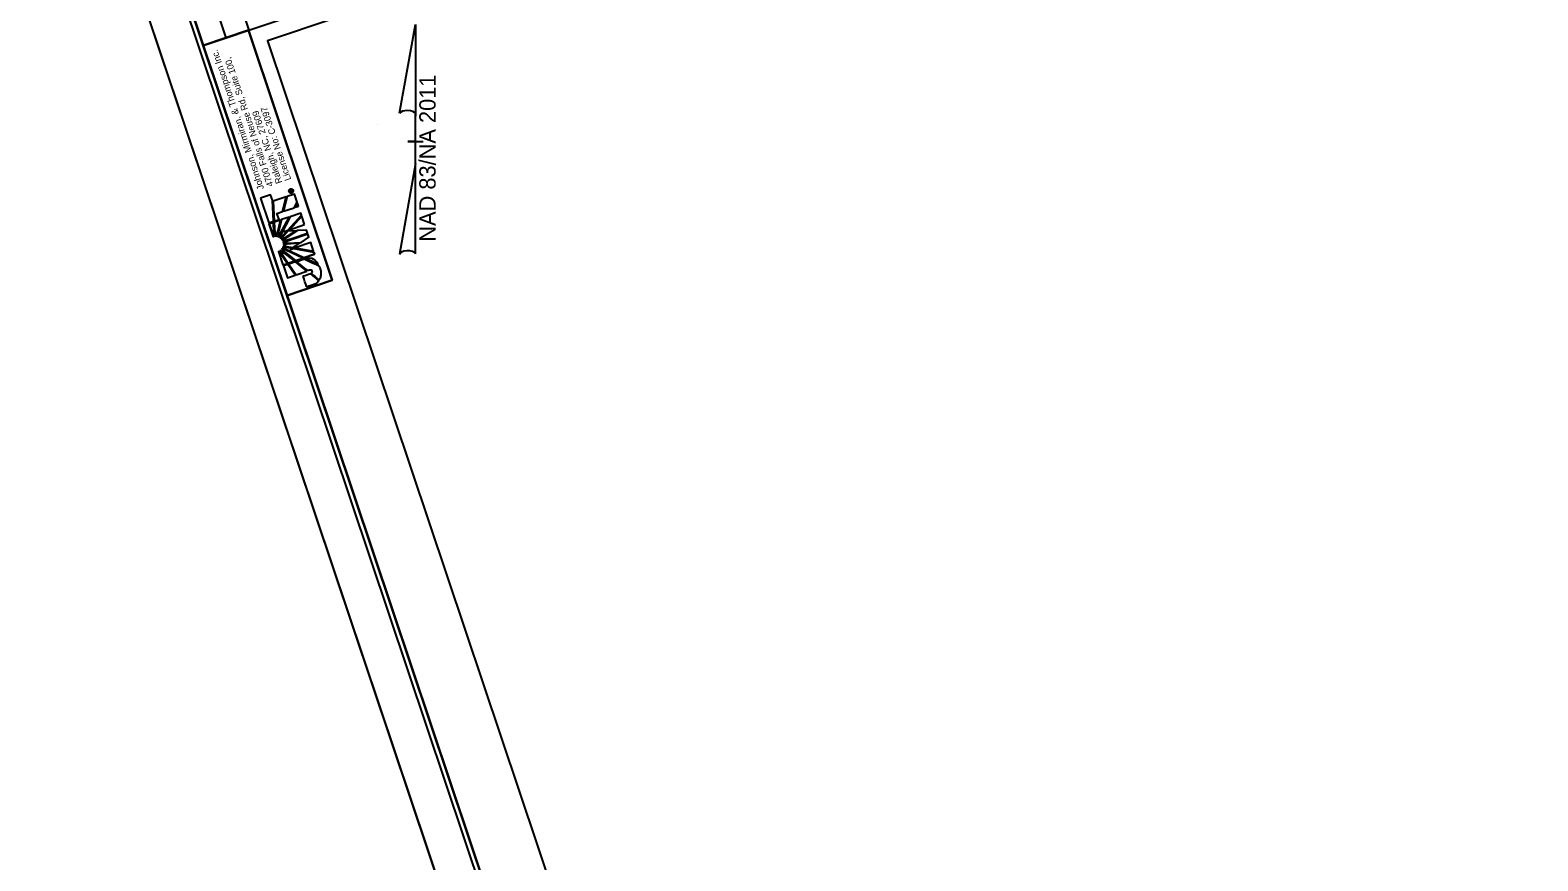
# Model space of a CAD drawing. Extents: x 1615436 to 1617010, y 903110 to 905055.
# Drawn here: x 1615436 to 1616223, y 904083 to 904516 of the extents above; entities that cross this region are included whole.
import ezdxf

# ---------------------------------------------------------------- set-up
doc = ezdxf.new("R2010")
doc.units = 0
for name, color, linetype in [('Default', 7, 'Continuous'), ('Exist Plan Preparation Drainage Flow Arrows', 7, 'Continuous'), ('Exist Plan Preparation Drainage Notes Label', 7, 'Continuous'), ('Exist Structure Minor Pipes CMP 24 Inch Text', 7, 'Continuous'), ('Exist Structure Minor Pipes RCP 18 Inch', 7, 'Continuous'), ('Prop Drainage Structure Catch Basin Grate 840 03E CELL', 7, 'Continuous'), ('Prop Drainage Structure Plot Symbol 50 Scale', 7, 'Continuous'), ('Prop Plan Preparation Sag Label', 7, 'Continuous'), ('Scratch_Level_8', 7, 'Continuous')]:
    doc.layers.add(name, color=color, linetype=linetype)

msp = doc.modelspace()

# ---------------------------------------------------------------- linework, layer by layer
at = {"layer": 'Default'}
for p, q in [((1615574.29, 904430.4), (1615570.5, 904429.12)), ((1615571.56, 904431.69), (1615571.75, 904431.76)), ((1615571.75, 904431.76), (1615571.56, 904431.69)), ((1615572.11, 904431.88), (1615572.09, 904431.93)), ((1615572.11, 904431.88), (1615572.29, 904431.94)), ((1615572.29, 904431.94), (1615572.11, 904431.88)), ((1615572.24, 904431.49), (1615572.11, 904431.88)), ((1615573.17, 904431.81), (1615572.24, 904431.49)), ((1615572.28, 904431.96), (1615572.29, 904431.94)), ((1615572.29, 904431.94), (1615572.34, 904431.77)), ((1615572.34, 904431.77), (1615572.56, 904431.84)), ((1615572.51, 904432.01), (1615572.5, 904432.02)), ((1615572.51, 904432.01), (1615572.68, 904432.07)), ((1615572.68, 904432.07), (1615572.51, 904432.01)), ((1615572.56, 904431.84), (1615572.51, 904432.01)), ((1615572.67, 904432.08), (1615572.68, 904432.07)), ((1615572.68, 904432.07), (1615572.73, 904431.9)), ((1615572.73, 904431.9), (1615573.1, 904432.02)), ((1615573.1, 904432.02), (1615573.17, 904431.81)), ((1615573.41, 904432.31), (1615573.4, 904432.32)), ((1615573.41, 904432.31), (1615573.61, 904432.38)), ((1615573.61, 904432.38), (1615573.41, 904432.31)), ((1615573.61, 904432.39), (1615573.61, 904432.38)), ((1615575.68, 904426.26), (1615574.29, 904430.4)), ((1615561.93, 904429.99), (1615556.67, 904428.22)), ((1615556.67, 904428.22), (1615560.99, 904415.4)), ((1615562.85, 904427.26), (1615561.93, 904429.99)), ((1615563.42, 904416.21), (1615562.85, 904427.26)), ((1615570.03, 904428.96), (1615563.3, 904426.69)), ((1615563.3, 904426.69), (1615563.78, 904416.34)), ((1615568.15, 904421.29), (1615570.03, 904428.96)), ((1615570.5, 904429.12), (1615568.66, 904421.46)), ((1615568.66, 904421.46), (1615574.11, 904423.3)), ((1615574.11, 904423.3), (1615575.68, 904426.26)), ((1615575.88, 904425.66), (1615574.7, 904423.5)), ((1615574.7, 904423.5), (1615576.42, 904424.08)), ((1615576.42, 904424.08), (1615575.88, 904425.66)), ((1615560.99, 904415.4), (1615563.35, 904416.19)), ((1615563.38, 904415.67), (1615561.18, 904414.93)), ((1615561.18, 904414.93), (1615563.43, 904408.16)), ((1615563.35, 904416.19), (1615563.42, 904416.21)), ((1615563.66, 904410.14), (1615563.38, 904415.67)), ((1615563.78, 904416.34), (1615563.82, 904416.35)), ((1615563.82, 904416.35), (1615566.28, 904417.18)), ((1615567.08, 904416.88), (1615563.84, 904415.83)), ((1615563.84, 904415.83), (1615564.16, 904410.12)), ((1615565.22, 904420.31), (1615568.15, 904421.29)), ((1615566.28, 904417.18), (1615565.22, 904420.31)), ((1615565.78, 904411.42), (1615567.08, 904416.88)), ((1615567.63, 904417.06), (1615566.06, 904410.69)), ((1615566.96, 904409.69), (1615571.53, 904418.37)), ((1615572.17, 904418.59), (1615567.36, 904409.52)), ((1615571.53, 904418.37), (1615567.63, 904417.06)), ((1615570.81, 904411.51), (1615578, 904419.36)), ((1615578.14, 904418.84), (1615571.68, 904411.8)), ((1615571.68, 904411.8), (1615579.62, 904414.47)), ((1615577.64, 904420.43), (1615572.17, 904418.59)), ((1615578, 904419.36), (1615577.64, 904420.43)), ((1615579.62, 904414.47), (1615578.14, 904418.84)), ((1615563.43, 904408.16), (1615563.66, 904410.14)), ((1615564.16, 904410.12), (1615564.55, 904408.16)), ((1615564.55, 904408.16), (1615565.78, 904411.42)), ((1615566.06, 904410.69), (1615565.68, 904407.94)), ((1615565.68, 904407.94), (1615566.96, 904409.69)), ((1615567.36, 904409.52), (1615566.65, 904407.47)), ((1615566.65, 904407.47), (1615568.36, 904408.88)), ((1615568.64, 904408.49), (1615567.49, 904406.79)), ((1615567.49, 904406.79), (1615569.37, 904407.65)), ((1615569.77, 904407.37), (1615568.09, 904405.91)), ((1615568.09, 904405.91), (1615573.01, 904407.22)), ((1615568.36, 904408.88), (1615570.34, 904411)), ((1615573.15, 904406.78), (1615568.43, 904404.9)), ((1615570.97, 904411.03), (1615568.64, 904408.49)), ((1615569.03, 904410.91), (1615570.81, 904411.51)), ((1615570.34, 904411), (1615569.03, 904410.91)), ((1615569.37, 904407.65), (1615575, 904411.31)), ((1615575.87, 904411.38), (1615569.77, 904407.37)), ((1615575, 904411.31), (1615570.97, 904411.03)), ((1615573.01, 904407.22), (1615581.14, 904409.95)), ((1615581.28, 904409.52), (1615573.15, 904406.78)), ((1615580.57, 904411.65), (1615575.87, 904411.38)), ((1615577.83, 904405.22), (1615581.85, 904407.85)), ((1615581.14, 904409.95), (1615580.57, 904411.65)), ((1615581.85, 904407.85), (1615581.28, 904409.52)), ((1615567.41, 904398.9), (1615566.05, 904400.39)), ((1615566.05, 904400.39), (1615568.36, 904393.53)), ((1615569.88, 904399.14), (1615566.97, 904400.97)), ((1615566.97, 904400.97), (1615567.89, 904399.06)), ((1615570.54, 904394.26), (1615567.41, 904398.9)), ((1615569.8, 904401.17), (1615567.75, 904401.79)), ((1615567.75, 904401.79), (1615569.71, 904399.86)), ((1615567.89, 904399.06), (1615571.02, 904394.42)), ((1615568.25, 904402.74), (1615570.04, 904401.54)), ((1615570.45, 904402.66), (1615568.25, 904402.74)), ((1615568.43, 904404.9), (1615570.66, 904404.72)), ((1615570.44, 904404.27), (1615568.5, 904403.8)), ((1615568.5, 904403.8), (1615570.45, 904403.12)), ((1615569.71, 904399.86), (1615574.85, 904395.71)), ((1615578.66, 904396.99), (1615569.8, 904401.17)), ((1615574.32, 904395.53), (1615569.88, 904399.14)), ((1615570.04, 904401.54), (1615579.3, 904397.21)), ((1615577.06, 904404.74), (1615570.44, 904404.27)), ((1615570.45, 904403.12), (1615573.72, 904402.53)), ((1615573.21, 904402.16), (1615570.45, 904402.66)), ((1615570.66, 904404.72), (1615577.83, 904405.22)), ((1615572.2, 904401.49), (1615573.21, 904402.16)), ((1615573.81, 904402.03), (1615572.2, 904401.49)), ((1615573.72, 904402.53), (1615577.06, 904404.74)), ((1615584.5, 904400.08), (1615573.81, 904402.03)), ((1615582.81, 904405.1), (1615574.69, 904402.32)), ((1615574.69, 904402.32), (1615584.34, 904400.55)), ((1615579.3, 904397.21), (1615584.84, 904399.08)), ((1615584.34, 904400.55), (1615582.81, 904405.1)), ((1615584.84, 904399.08), (1615584.5, 904400.08)), ((1615568.36, 904393.53), (1615570.54, 904394.26)), ((1615570.96, 904393.7), (1615568.6, 904392.9)), ((1615568.6, 904392.9), (1615570.66, 904386.8)), ((1615574.7, 904388.17), (1615570.96, 904393.7)), ((1615571.02, 904394.42), (1615574.32, 904395.53)), ((1615574.93, 904395.03), (1615571.4, 904393.84)), ((1615571.4, 904393.84), (1615575.17, 904388.32)), ((1615574.85, 904395.71), (1615578.66, 904396.99)), ((1615580.85, 904390.24), (1615574.93, 904395.03)), ((1615570.66, 904386.8), (1615574.7, 904388.17)), ((1615575.17, 904388.32), (1615580.85, 904390.24))]:
    msp.add_line(p, q, dxfattribs=at)
for points in [[(1615594.07, 904385.48), (1615550.29, 904515.85), (1615526.77, 904507.96), (1615570.54, 904377.58)], [(1615563.43, 904408.16), (1615561.18, 904414.93), (1615563.38, 904415.67), (1615563.66, 904410.14)], [(1615584.84, 904399.08), (1615579.3, 904397.21), (1615570.04, 904401.54), (1615568.25, 904402.74), (1615569.97, 904402.73), (1615573.21, 904402.16), (1615572.2, 904401.49), (1615573.81, 904402.03), (1615584.5, 904400.08)]]:
    msp.add_lwpolyline(points, close=True, dxfattribs=at)
for points in [[(1615568.66, 904421.46), (1615574.11, 904423.3), (1615575.68, 904426.26), (1615574.29, 904430.4), (1615570.5, 904429.12), (1615568.66, 904421.46), (1615568.66, 904421.46)], [(1615572.68, 904432.52), (1615572.73, 904432.54), (1615572.77, 904432.56), (1615572.8, 904432.57), (1615572.89, 904432.63), (1615572.96, 904432.44)], [(1615556.67, 904428.22), (1615560.99, 904415.4), (1615563.35, 904416.19), (1615563.42, 904416.21), (1615562.85, 904427.26), (1615561.93, 904429.99), (1615556.67, 904428.22)], [(1615563.78, 904416.34), (1615563.82, 904416.35), (1615566.28, 904417.18), (1615565.22, 904420.31), (1615568.15, 904421.29), (1615570.03, 904428.96), (1615563.3, 904426.69), (1615563.78, 904416.34)], [(1615576.42, 904424.08), (1615576.42, 904424.08), (1615575.88, 904425.66), (1615574.7, 904423.5), (1615576.42, 904424.08)], [(1615563.66, 904410.14), (1615563.38, 904415.67), (1615561.18, 904414.93), (1615563.43, 904408.16), (1615563.66, 904410.14)], [(1615564.55, 904408.16), (1615565.78, 904411.42), (1615567.08, 904416.88), (1615563.84, 904415.83), (1615564.16, 904410.12), (1615564.55, 904408.16)], [(1615565.68, 904407.94), (1615566.96, 904409.69), (1615571.53, 904418.37), (1615567.63, 904417.06), (1615566.06, 904410.69), (1615565.68, 904407.94)], [(1615566.65, 904407.47), (1615568.36, 904408.88), (1615570.34, 904411), (1615569.03, 904410.91), (1615570.81, 904411.51), (1615578, 904419.36), (1615577.64, 904420.43), (1615572.17, 904418.59), (1615567.36, 904409.52), (1615566.65, 904407.47)], [(1615579.62, 904414.47), (1615578.14, 904418.84), (1615571.68, 904411.8), (1615579.62, 904414.47)], [(1615567.49, 904406.79), (1615569.37, 904407.65), (1615575, 904411.31), (1615570.97, 904411.03), (1615568.64, 904408.49), (1615567.49, 904406.79)], [(1615568.09, 904405.91), (1615573.01, 904407.22), (1615581.14, 904409.95), (1615580.57, 904411.65), (1615575.87, 904411.38), (1615569.77, 904407.37), (1615568.09, 904405.91)], [(1615570.66, 904404.72), (1615577.83, 904405.22), (1615581.85, 904407.85), (1615581.28, 904409.52), (1615573.15, 904406.78), (1615568.43, 904404.9), (1615570.66, 904404.72)], [(1615567.41, 904398.9), (1615566.05, 904400.39), (1615568.36, 904393.53), (1615570.54, 904394.26), (1615567.41, 904398.9)], [(1615571.02, 904394.42), (1615574.32, 904395.53), (1615569.88, 904399.14), (1615566.97, 904400.97), (1615567.89, 904399.06), (1615571.02, 904394.42)], [(1615574.85, 904395.71), (1615578.66, 904396.99), (1615569.8, 904401.17), (1615567.75, 904401.79), (1615569.71, 904399.86), (1615574.85, 904395.71)], [(1615568.25, 904402.74), (1615570.04, 904401.54), (1615579.3, 904397.21), (1615584.84, 904399.08), (1615584.5, 904400.08), (1615573.81, 904402.03), (1615572.2, 904401.49), (1615573.21, 904402.16), (1615570.45, 904402.66), (1615568.25, 904402.74)], [(1615568.5, 904403.8), (1615570.45, 904403.12), (1615573.72, 904402.53), (1615577.06, 904404.74), (1615570.44, 904404.27), (1615568.5, 904403.8)], [(1615584.34, 904400.55), (1615582.81, 904405.1), (1615574.69, 904402.32), (1615584.34, 904400.55)], [(1615574.7, 904388.17), (1615570.96, 904393.7), (1615568.6, 904392.9), (1615570.66, 904386.8), (1615574.7, 904388.17)], [(1615580.85, 904390.24), (1615574.93, 904395.03), (1615571.4, 904393.84), (1615575.17, 904388.32), (1615580.85, 904390.24)]]:
    msp.add_lwpolyline(points, dxfattribs=at)
for points, degree in [([(1615571.56, 904431.69), (1615571.46, 904431.98), (1615571.48, 904432.26), (1615571.61, 904432.53), (1615571.72, 904432.79), (1615571.94, 904432.98), (1615572.22, 904433.08)], 3), ([(1615573.61, 904432.38), (1615573.7, 904432.1), (1615573.68, 904431.82), (1615573.55, 904431.55), (1615573.42, 904431.28), (1615573.21, 904431.1), (1615572.92, 904431), (1615572.63, 904430.9), (1615572.35, 904430.92), (1615572.1, 904431.06), (1615571.84, 904431.2), (1615571.65, 904431.4), (1615571.56, 904431.69)], 3), ([(1615573.4, 904432.32), (1615573.33, 904432.55), (1615573.18, 904432.72), (1615572.97, 904432.83), (1615572.75, 904432.93), (1615572.52, 904432.95), (1615572.29, 904432.87), (1615572.06, 904432.79), (1615571.89, 904432.64), (1615571.78, 904432.43), (1615571.68, 904432.21), (1615571.67, 904431.99), (1615571.75, 904431.76)], 3), ([(1615571.75, 904431.76), (1615571.83, 904431.53), (1615571.97, 904431.36), (1615572.18, 904431.25), (1615572.39, 904431.14), (1615572.63, 904431.12), (1615572.85, 904431.2), (1615573.08, 904431.28), (1615573.26, 904431.43), (1615573.37, 904431.65), (1615573.47, 904431.86), (1615573.48, 904432.08), (1615573.41, 904432.31)], 3), ([(1615572.09, 904431.93), (1615572.01, 904432.17), (1615572.06, 904432.32), (1615572.25, 904432.39), (1615572.33, 904432.41), (1615572.41, 904432.4), (1615572.49, 904432.34)], 3), ([(1615572.22, 904433.08), (1615572.51, 904433.17), (1615572.79, 904433.15), (1615573.06, 904433.03), (1615573.32, 904432.89), (1615573.51, 904432.68), (1615573.61, 904432.39)], 3), ([(1615572.5, 904432.02), (1615572.46, 904432.15), (1615572.39, 904432.21), (1615572.32, 904432.18), (1615572.25, 904432.16), (1615572.24, 904432.09), (1615572.28, 904431.96)], 3), ([(1615572.49, 904432.34), (1615572.5, 904432.41), (1615572.57, 904432.47), (1615572.68, 904432.52)], 2), ([(1615572.96, 904432.44), (1615572.92, 904432.39), (1615572.87, 904432.36), (1615572.8, 904432.34), (1615572.72, 904432.31), (1615572.67, 904432.28), (1615572.65, 904432.25)], 3), ([(1615572.65, 904432.25), (1615572.65, 904432.22), (1615572.65, 904432.16), (1615572.67, 904432.08)], 2), ([(1615583.61, 904390.19), (1615583.74, 904389.83), (1615583.64, 904389.45), (1615583.01, 904389.09), (1615583.01, 904389.09), (1615587.19, 904385.63), (1615587.19, 904385.63), (1615588.16, 904387.45), (1615588.28, 904389.89), (1615587.66, 904391.71), (1615587.5, 904392.19), (1615587.34, 904392.53), (1615587.07, 904393), (1615587.07, 904393), (1615579.54, 904396.59), (1615579.54, 904396.59), (1615579.54, 904396.59), (1615575.44, 904395.2), (1615575.44, 904395.2), (1615575.44, 904395.2), (1615581.37, 904390.41), (1615581.37, 904390.41), (1615582.91, 904390.93), (1615583.44, 904390.69), (1615583.61, 904390.19)], 3), ([(1615583.61, 904390.19), (1615583.74, 904389.83), (1615583.64, 904389.45), (1615583.01, 904389.09), (1615583.01, 904389.09), (1615587.19, 904385.63), (1615587.19, 904385.63), (1615588.16, 904387.45), (1615588.28, 904389.89), (1615587.66, 904391.71), (1615587.5, 904392.19), (1615587.34, 904392.53), (1615587.07, 904393), (1615587.07, 904393), (1615579.54, 904396.59), (1615579.54, 904396.59), (1615579.54, 904396.59), (1615575.44, 904395.2), (1615575.44, 904395.2), (1615575.44, 904395.2), (1615581.37, 904390.41), (1615581.37, 904390.41), (1615582.91, 904390.93), (1615583.44, 904390.69), (1615583.61, 904390.19)], 3), ([(1615580.19, 904396.8), (1615580.19, 904396.8), (1615586.69, 904393.7), (1615586.69, 904393.7), (1615585.33, 904395.84), (1615583.01, 904397.63), (1615580.19, 904396.8)], 3), ([(1615578.83, 904387.6), (1615578.83, 904387.6), (1615580.73, 904381.96), (1615580.73, 904381.96), (1615580.73, 904381.96), (1615584.26, 904383.15), (1615584.26, 904383.15), (1615584.26, 904383.15), (1615584.63, 904383.27), (1615584.63, 904383.27), (1615585.74, 904383.65), (1615586.49, 904384.3), (1615587.01, 904385.19), (1615587.01, 904385.19), (1615582.63, 904388.89), (1615582.56, 904388.86), (1615582.56, 904388.86), (1615578.83, 904387.6), (1615578.83, 904387.6)], 3)]:
    msp.add_open_spline(points, degree=degree, dxfattribs=at)
at = {"layer": 'Exist Plan Preparation Drainage Flow Arrows'}
msp.add_lwpolyline([(1616986.86, 903464.68), (1616457.04, 905044.17), (1615456.82, 904708.68), (1615986.63, 903129.17)], close=True, dxfattribs=at)
at = {"layer": 'Exist Plan Preparation Drainage Notes Label'}
msp.add_lwpolyline([(1617009.96, 903458.71), (1616474.57, 905054.81), (1615436.42, 904706.58), (1615971.81, 903110.48)], close=True, dxfattribs=at)
at = {"layer": 'Exist Structure Minor Pipes CMP 24 Inch Text'}
msp.add_line((1615436.42, 904706.58), (1615971.81, 903110.48), dxfattribs=at)
at = {"layer": 'Exist Structure Minor Pipes RCP 18 Inch'}
msp.add_lwpolyline([(1615570.54, 904377.58), (1615526.76, 904507.95), (1615550.29, 904515.85), (1615594.08, 904385.49)], close=True, dxfattribs=at)
at = {"layer": 'Prop Drainage Structure Catch Basin Grate 840 03E CELL'}
msp.add_lwpolyline([(1616672.58, 903656.2), (1616919.77, 903656.8), (1616590.65, 904611.24), (1616386.84, 904624.44), (1616334.81, 904821.64), (1616466, 905009.57), (1615641.09, 904732.87), (1615700.02, 904557.19), (1615560.35, 904510.33), (1615954.19, 903336.21)], close=True, dxfattribs=at)
at = {"layer": 'Prop Drainage Structure Plot Symbol 50 Scale'}
msp.add_line((1615617.56, 904466.62), (1615617.56, 904466.62), dxfattribs=at)
at = {"layer": 'Prop Plan Preparation Sag Label'}
for p, q in [((1615629.23, 904472.53), (1615637.43, 904518.88)), ((1615637.48, 904518.88), (1615637.48, 904471.08)), ((1615558.76, 904489.51), (1615558.72, 904489.48)), ((1615558.76, 904489.51), (1615558.72, 904489.48)), ((1615637.48, 904446.28), (1615637.48, 904472.48)), ((1615637.48, 904471.08), (1615637.48, 904472.43)), ((1615633.48, 904457.88), (1615633.43, 904457.88)), ((1615637.03, 904457.88), (1615633.48, 904457.88)), ((1615633.53, 904457.88), (1615641.53, 904457.88)), ((1615637.48, 904446.28), (1615629.13, 904399.03)), ((1615637.53, 904399.23), (1615637.48, 904446.28))]:
    msp.add_line(p, q, dxfattribs=at)
for centre, start_param, end_param in [((1615633.36, 904472.03), 0.216388, 2.908219), ((1615633.36, 904398.86), 0.201328, 3.141593)]:
    msp.add_ellipse(centre, major_axis=(4.23, -0.03), ratio=0.461098, start_param=start_param, end_param=end_param, dxfattribs=at)
at = {"layer": 'Scratch_Level_8'}
msp.add_line((1615538.66, 904511.93), (1615475.05, 904701.6), dxfattribs=at)
for points in [[(1615463.14, 904697.64), (1615940.18, 903275.48), (1616935.67, 903609.4), (1616458.64, 905031.54)], [(1616935.67, 903609.4), (1615940.21, 903275.46), (1615526.76, 904507.95), (1615669.02, 904555.68), (1615605.42, 904745.34), (1616458.64, 905031.54)], [(1615526.76, 904507.95), (1615463.14, 904697.64), (1615486.9, 904705.57), (1615550.54, 904515.93)]]:
    msp.add_lwpolyline(points, close=True, dxfattribs=at)

# ---------------------------------------------------------------- texts
at = {"layer": 'Default'}
for s, height, p in [('Johnson, Mirmiran, & Thompson Inc.', 3.5139, (1615558.54, 904433.3)), ('4700 Falls of Neuse Rd, Suite 100, ', 3.4135, (1615563.43, 904434.94)), ('Raleigh, NC, 27609', 3.4135, (1615568.05, 904436.49)), ('License No: C-3097', 3.4135, (1615572.68, 904438.04))]:
    msp.add_text(s, height=height, rotation=108.55966, dxfattribs=at).set_placement(p)
at = {"layer": 'Prop Plan Preparation Sag Label'}
msp.add_text('NAD 83/NA 2011', height=8.5, rotation=90, dxfattribs=at).set_placement((1615648, 904405.57))

doc.saveas('drawing.dxf')
